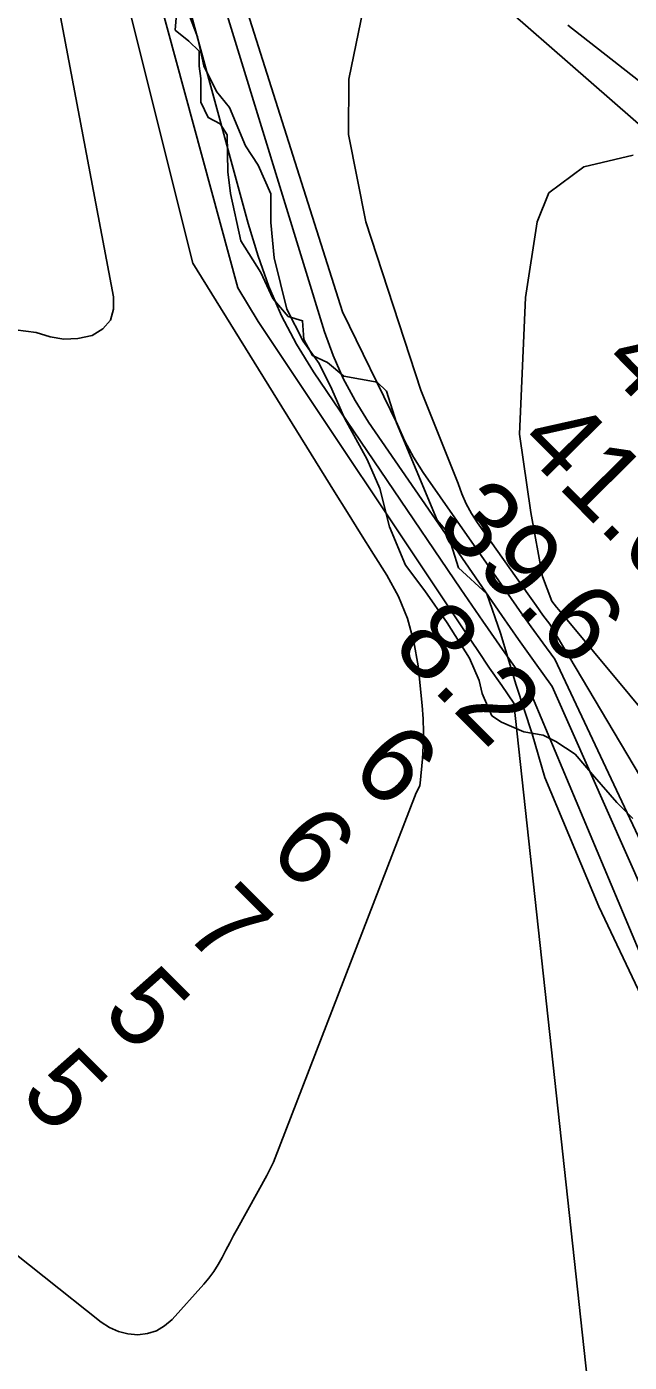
# Model space of a CAD drawing. Extents: x 3161615 to 3199515, y 867541 to 892976.
# Drawn here: x 3182184 to 3182704, y 881302 to 882454 of the extents above; entities that cross this region are included whole.
import ezdxf

# ---------------------------------------------------------------- set-up
doc = ezdxf.new("R2010")
doc.units = 0
for name, color, linetype in [('V-RIVR-EDGE', 7, 'Continuous'), ('V-RIVR-RANG', 7, 'Continuous'), ('V-SITE-VEGE', 7, 'Continuous'), ('V-TOPO-DPTH', 7, 'Continuous'), ('V-TOPO-MAJR', 7, 'Continuous'), ('V-TOPO-MINR', 7, 'Continuous'), ('V-TOPO-WATR', 7, 'Continuous')]:
    doc.layers.add(name, color=color, linetype=linetype)

msp = doc.modelspace()

# ---------------------------------------------------------------- linework, layer by layer
at = {"layer": 'V-RIVR-EDGE'}
msp.add_lwpolyline([(3182713.9, 881618.3), (3182677.4, 881695.2), (3182630.9, 881806.4), (3182620.1, 881844.1), (3182606.3, 881886.1), (3182592.6, 881931), (3182580.8, 881964.9), (3182556.5, 881987.3), (3182546.6, 882018.4), (3182538, 882028.4), (3182520, 882071.8), (3182502.9, 882112.4), (3182494.4, 882139.6), (3182486.3, 882147.3), (3182457.7, 882152.6), (3182443.4, 882164.5), (3182430.6, 882170.3), (3182423, 882184.1), (3182422.1, 882200.4), (3182409.7, 882204.2), (3182396.4, 882219.5), (3182385.9, 882241.9), (3182368.8, 882269.2), (3182359.9, 882310.2), (3182357.5, 882328.8), (3182357.1, 882360.7), (3182351, 882370.3), (3182340.5, 882375.6), (3182334.3, 882388.9), (3182334.4, 882409.4), (3182333, 882419.9), (3182333, 882432.8), (3182324, 882441.4), (3182312.1, 882451), (3182313, 882461.5)], dxfattribs=at)
at = {"layer": 'V-SITE-VEGE'}
for points in [[(3182582.5, 882483.1), (3182759, 882328.7), (3182770.5, 882320), (3182784.9, 882305.8), (3182863.6, 882237.7), (3182888.8, 882210.5), (3183025.9, 882091.1), (3183183.9, 881963.9), (3183285.3, 881878), (3183322.1, 881850.8), (3183332.3, 881838.5), (3183336.3, 881835), (3183449.1, 881746.6), (3183463.7, 881732.6), (3183610.1, 881617.8), (3183727.1, 881529.7), (3183827.7, 881452.8)], [(3182706.8, 881771.3), (3182693, 881785.1), (3182673.7, 881807.2), (3182657.1, 881826.5), (3182640.5, 881837.6), (3182629.5, 881843.1), (3182612.9, 881845.9), (3182593.6, 881854.2), (3182585.3, 881859.7), (3182577, 881879), (3182574.3, 881890.1), (3182566, 881909.4), (3182546.7, 881939.8), (3182527.4, 881967.4), (3182510.8, 881989.5), (3182497, 882022.6), (3182488.7, 882055.7), (3182477.7, 882080.6), (3182458.3, 882116.5), (3182447.3, 882141.4), (3182436.3, 882163.4), (3182422.4, 882182.8), (3182408.6, 882210.4), (3182397.6, 882254.6), (3182394.8, 882285), (3182394.8, 882309.8), (3182383.8, 882334.7), (3182372.8, 882351.2), (3182358.9, 882384.4), (3182347.9, 882398.2), (3182336.9, 882420.3), (3182331.3, 882445.1), (3182323.1, 882467.2)]]:
    msp.add_lwpolyline(points, dxfattribs=at)
at = {"layer": 'V-TOPO-DPTH'}
for points in [[(3181405.9, 883096.7), (3181801, 882360.4), (3181804.8, 882354.3), (3181809.1, 882348.7), (3181813.9, 882343.2), (3181896.8, 882256.1), (3181907.2, 882246.2), (3181918.3, 882237.2), (3181930.2, 882229.4), (3181942.7, 882222.4), (3182192.4, 882190.4), (3182204.3, 882186.4), (3182216.3, 882184.4), (3182228.4, 882185.1), (3182240.6, 882187.7), (3182249.8, 882193.5), (3182256.3, 882200.8), (3182259, 882210.3), (3182259, 882221.1), (3182179.9, 882639.1)], [(3182179.9, 882639.1), (3182259, 882221.1), (3182259, 882210.3), (3182256.3, 882200.8), (3182249.8, 882193.5), (3182240.6, 882187.7), (3182228.4, 882185.1), (3182216.3, 882184.4), (3182204.3, 882186.4), (3182192.4, 882190.4), (3181942.7, 882222.4), (3181930.2, 882229.4), (3181918.3, 882237.2), (3181907.2, 882246.2), (3181896.8, 882256.1), (3181813.9, 882343.2), (3181809.1, 882348.7), (3181804.8, 882354.3), (3181801, 882360.4), (3181405.9, 883096.7)], [(3182688.7, 881092.9), (3182604.3, 881870.7), (3182593.8, 881885.8), (3182583.3, 881900.9), (3182573, 881916.1), (3182562.8, 881931.4), (3182383.8, 882199.8), (3182366.3, 882228.7), (3182244.3, 882677.5)], [(3182688.7, 881092.9), (3182604.3, 881870.7), (3182593.8, 881885.8), (3182583.3, 881900.9), (3182573, 881916.1), (3182562.8, 881931.4), (3182383.8, 882199.8), (3182366.3, 882228.7), (3182244.3, 882677.5)], [(3182293.8, 882669.9), (3182441, 882190.9), (3182448.4, 882170.4), (3182457, 882150.5), (3182467.3, 882131.5), (3182478.8, 882113), (3182579.7, 881966.6), (3182593.9, 881946.1), (3182608.2, 881925.6), (3182622.7, 881905.3), (3182637.3, 881885), (3182925.1, 881235.7)]]:
    msp.add_lwpolyline(points, dxfattribs=at)
at = {"layer": 'V-TOPO-MAJR'}
msp.add_lwpolyline([(3182856.5, 881694.4), (3182643, 881951), (3182640.9, 881953.5), (3182638.9, 881956.1), (3182636.9, 881958.7), (3182628.8, 881979.9), (3182618.9, 882035), (3182609, 882102.7), (3182614.2, 882220.5), (3182624.3, 882285.6), (3182634.4, 882310.6), (3182664.5, 882333.1), (3182707.1, 882343.1)], dxfattribs=at)
at = {"layer": 'V-TOPO-MINR'}
for points in [[(3181405.9, 883096.7), (3181801, 882360.4), (3181804.8, 882354.3), (3181809.1, 882348.7), (3181813.9, 882343.2), (3181896.8, 882256.1), (3181907.2, 882246.2), (3181918.3, 882237.2), (3181930.2, 882229.4), (3181942.7, 882222.4), (3182192.4, 882190.4), (3182204.3, 882186.4), (3182216.3, 882184.4), (3182228.4, 882185.1), (3182240.6, 882187.7), (3182249.8, 882193.5), (3182256.3, 882200.8), (3182259, 882210.3), (3182259, 882221.1), (3182179.9, 882639.1)], [(3182149.7, 881414.9), (3182248.4, 881336.9), (3182255.6, 881332.2), (3182263.2, 881328.7), (3182271.4, 881326.8), (3182279.9, 881325.9), (3182288.3, 881327), (3182296.1, 881329.3), (3182303.1, 881333.6), (3182309.5, 881339), (3182336.8, 881369.5), (3182341.3, 881374.9), (3182345.5, 881380.5), (3182349.2, 881386.5), (3182352.7, 881392.6), (3182355.9, 881398.9), (3182359.2, 881405.2), (3182362.6, 881411.5), (3182366, 881417.7), (3182391.2, 881463.2), (3182394.2, 881469), (3182396.9, 881474.9), (3182520.1, 881793.4), (3182521.8, 881796.4), (3182523, 881799.5), (3182523.4, 881801.6), (3182525.3, 881822.5), (3182526.1, 881834), (3182526.3, 881845.5), (3182525.9, 881857), (3182525.1, 881868.5), (3182521.6, 881902.9), (3182518, 881923.5), (3182512.6, 881943.5), (3182504.6, 881962.6), (3182494.6, 881981), (3182483.3, 881999), (3182472.1, 882017), (3182460.8, 882035), (3182449.6, 882053), (3182327.3, 882250.1), (3182219.6, 882681.3)], [(3183469, 879013.6), (3183197.7, 880018.7), (3183198.1, 880021.4), (3183197.8, 880022.8), (3183196, 880027.2), (3183194.9, 880029.5), (3183193.6, 880031.8), (3183192.2, 880034.1), (3183181.6, 880049.9), (3183030.2, 880674), (3182912.2, 881192.2), (3182899.3, 881211.2), (3182615.6, 881886.6), (3182596.4, 881913.9), (3182577.5, 881941.3), (3182558.6, 881968.9), (3182431.4, 882156.4), (3182416.9, 882180.1), (3182403.8, 882204.5), (3182393, 882229.9), (3182383.6, 882256.1), (3182375, 882284.4), (3182269.1, 882673.7)], [(3182925.1, 881235.7), (3182637.3, 881885), (3182622.7, 881905.3), (3182608.2, 881925.6), (3182593.9, 881946.1), (3182579.7, 881966.6), (3182478.8, 882113), (3182467.3, 882131.5), (3182457, 882150.5), (3182448.4, 882170.4), (3182441, 882190.9), (3182293.8, 882669.9)], [(3182949.6, 881249.7), (3182639.4, 881908.7), (3182629.3, 881922.6), (3182619.2, 881936.5), (3182609.2, 881950.6), (3182599.3, 881964.6), (3182525.9, 882069.6), (3182517.6, 882082.8), (3182510.1, 882096.5), (3182503.8, 882110.8), (3182456.4, 882208.2), (3182369.2, 882483.9)], [(3183013.3, 881300.1), (3183006.2, 881313.9), (3182635.3, 881938.6), (3182629.3, 881946.6), (3182623.5, 881954.7), (3182617.7, 881962.9), (3182572.8, 882026.2), (3182567.7, 882034.2), (3182563.1, 882042.5), (3182559.3, 882051.1), (3182556.1, 882060.1), (3182523.9, 882140.4), (3182476.6, 882285.8), (3182461.7, 882361), (3182461.8, 882408.6), (3182474.4, 882468.7)], [(3182650.7, 882455.4), (3182919.4, 882245)]]:
    msp.add_lwpolyline(points, dxfattribs=at)
at = {"layer": 'V-TOPO-WATR'}
msp.add_lwpolyline([(3182688.7, 881092.9), (3182604.3, 881870.7), (3182593.8, 881885.8), (3182583.3, 881900.9), (3182573, 881916.1), (3182562.8, 881931.4), (3182383.8, 882199.8), (3182366.3, 882228.7), (3182244.3, 882677.5)], dxfattribs=at)

# ---------------------------------------------------------------- texts
at = {"layer": 'V-RIVR-RANG'}
for s, rotation, p in [('42.8', 314.6583, (3182678.1, 882162.5)), ('41.6', 314.6583, (3182605.8, 882093.3)), ('39.6', 314.6583, (3182534.9, 882022.9)), ('8.2', 314.8431, (3182497.6, 881918)), ('6', 314.8431, (3182461.6, 881812.4)), ('6', 314.8431, (3182390.6, 881741.9)), ('7', 314.8431, (3182317.8, 881673.3)), ('5', 314.8431, (3182247.6, 881602.1)), ('5', 314.8431, (3182176.6, 881531.7))]:
    msp.add_text(s, height=67, rotation=rotation, dxfattribs=at).set_placement(p)

doc.saveas('drawing.dxf')
